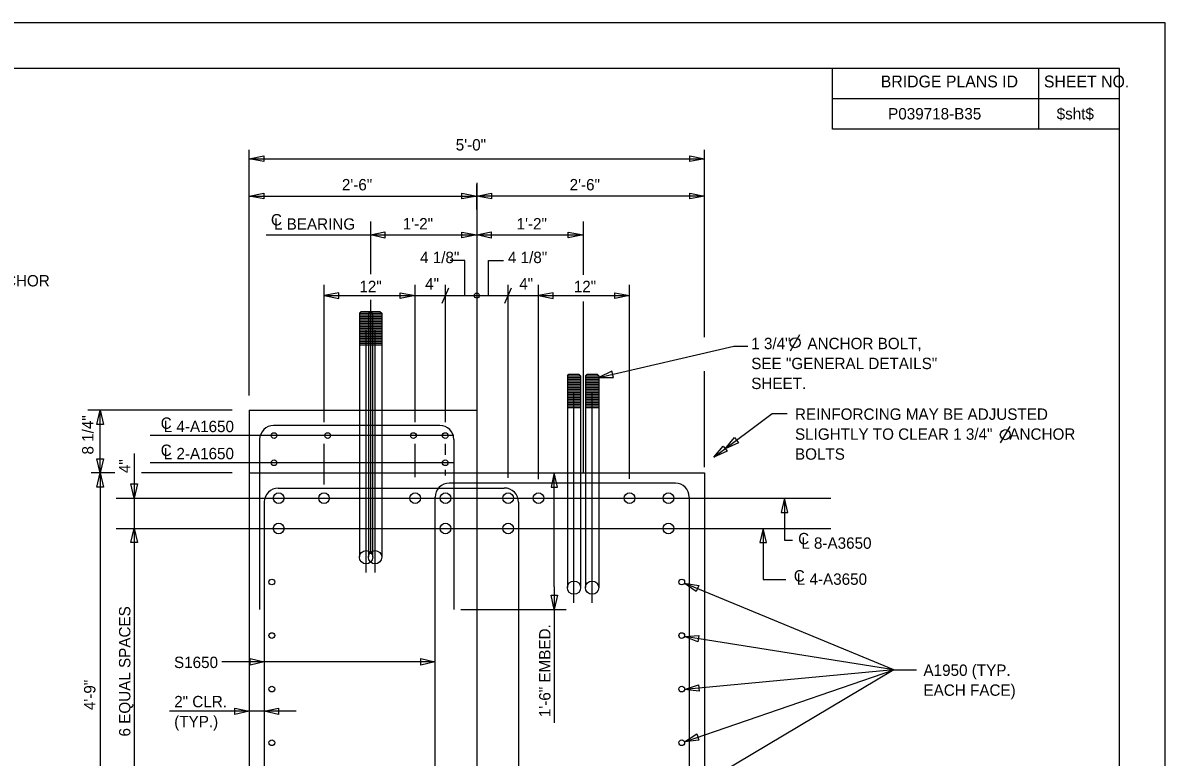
# Model space of a CAD drawing. Extents: x -133.1 to -97, y -1.7 to 20.3.
# Drawn here: x -109.68 to -97.14, y 12.24 to 20.31 of the extents above; entities that cross this region are included whole.
import ezdxf

# ---------------------------------------------------------------- set-up
doc = ezdxf.new("R2010")
doc.units = 0
for name, color, linetype in [('BR_AUTO DIMENSION', 7, 'Continuous'), ('BR_BORDER LINES', 7, 'Continuous'), ('BR_CENTER LINES', 7, 'Continuous'), ('BR_CONCRETE', 7, 'Continuous'), ('BR_REBAR', 7, 'Continuous'), ('BR_STRUCTURAL STEEL', 7, 'Continuous'), ('BR_TEXT', 7, 'Continuous'), ('Level 31', 7, 'Continuous')]:
    doc.layers.add(name, color=color, linetype=linetype)

msp = doc.modelspace()

# ---------------------------------------------------------------- linework, layer by layer
at = {"layer": 'BR_AUTO DIMENSION'}
for p, q in [((-107.198, 16.216), (-107.198, 18.914)), ((-107.198, 18.817), (-102.198, 18.817)), ((-102.198, 16.857), (-102.198, 18.914)), ((-104.698, 18.258), (-104.698, 18.534)), ((-107.198, 18.406), (-104.698, 18.406)), ((-102.198, 18.406), (-104.698, 18.406)), ((-107.012, 17.979), (-103.532, 17.979)), ((-104.828, 17.699), (-104.992, 17.699)), ((-104.828, 17.314), (-104.828, 17.699)), ((-104.568, 17.314), (-104.568, 17.699)), ((-104.568, 17.699), (-104.404, 17.699)), ((-106.375, 15.923), (-106.375, 17.432)), ((-105.375, 15.923), (-105.375, 17.432)), ((-105.042, 15.923), (-105.042, 17.432)), ((-104.354, 15.313), (-104.354, 17.432)), ((-104.021, 15.297), (-104.021, 17.432)), ((-103.021, 15.302), (-103.021, 17.432)), ((-106.375, 17.314), (-103.021, 17.314)), ((-105.079, 17.231), (-105.005, 17.397)), ((-104.392, 17.231), (-104.317, 17.397)), ((-103.359, 16.414), (-101.877, 16.758)), ((-101.877, 16.758), (-101.723, 16.758)), ((-102.198, 15.429), (-102.198, 16.483)), ((-107.384, 16.054), (-108.969, 16.054)), ((-108.833, 15.366), (-108.833, 16.054)), ((-106.375, 15.239), (-106.375, 15.684)), ((-105.375, 15.319), (-105.375, 15.684)), ((-105.042, 15.565), (-105.042, 15.684)), ((-108.459, 15.581), (-108.459, 10.355)), ((-108.671, 15.366), (-108.931, 15.366)), ((-108.833, 15.366), (-108.834, 10.616)), ((-107.385, 15.366), (-108.38, 15.366)), ((-105.042, 15.336), (-105.042, 15.401)), ((-103.847, 14.116), (-103.847, 15.366)), ((-101.555, 14.756), (-101.555, 14.194)), ((-101.555, 14.194), (-101.304, 14.194)), ((-103.847, 14.116), (-103.847, 12.621)), ((-100.118, 13.205), (-102.42, 14.155)), ((-104.872, 13.866), (-103.716, 13.866)), ((-100.118, 13.205), (-102.418, 13.57)), ((-105.157, 13.292), (-107.497, 13.292)), ((-100.118, 13.205), (-102.422, 11.832)), ((-100.118, 13.205), (-102.417, 12.989)), ((-106.68, 12.748), (-108.072, 12.748))]:
    msp.add_line(p, q, dxfattribs=at)
for points in [[(-107.036, 18.785), (-107.198, 18.817), (-107.036, 18.848)], [(-102.361, 18.848), (-102.198, 18.817), (-102.361, 18.785)], [(-107.036, 18.375), (-107.198, 18.406), (-107.036, 18.437)], [(-104.861, 18.437), (-104.698, 18.406), (-104.861, 18.375)], [(-104.536, 18.375), (-104.698, 18.406), (-104.536, 18.437)], [(-102.361, 18.437), (-102.198, 18.406), (-102.361, 18.375)], [(-105.709, 17.943), (-105.865, 17.979), (-105.709, 18.015)], [(-104.861, 18.01), (-104.698, 17.979), (-104.861, 17.948)], [(-104.542, 17.943), (-104.698, 17.979), (-104.542, 18.015)], [(-103.694, 18.01), (-103.532, 17.979), (-103.694, 17.948)], [(-106.213, 17.345), (-106.375, 17.314), (-106.213, 17.283)], [(-105.538, 17.345), (-105.375, 17.314), (-105.538, 17.283)], [(-103.859, 17.345), (-104.021, 17.314), (-103.859, 17.283)], [(-103.184, 17.345), (-103.021, 17.314), (-103.184, 17.283)], [(-103.215, 16.484), (-103.359, 16.414), (-103.199, 16.414)], [(-108.869, 15.898), (-108.833, 16.054), (-108.797, 15.898)], [(-101.824, 15.697), (-101.971, 15.632), (-101.868, 15.755)], [(-101.949, 15.604), (-102.096, 15.539), (-101.993, 15.661)], [(-108.797, 15.522), (-108.833, 15.366), (-108.869, 15.522)], [(-108.869, 15.21), (-108.833, 15.366), (-108.797, 15.21)], [(-103.811, 15.21), (-103.847, 15.366), (-103.883, 15.21)], [(-108.423, 15.245), (-108.459, 15.089), (-108.495, 15.245)], [(-101.283, 14.933), (-101.319, 15.089), (-101.355, 14.933)], [(-108.495, 14.6), (-108.459, 14.756), (-108.423, 14.6)], [(-101.519, 14.6), (-101.555, 14.756), (-101.591, 14.6)], [(-102.289, 14.062), (-102.42, 14.155), (-102.262, 14.129)], [(-103.811, 14.022), (-103.847, 13.866), (-103.883, 14.022)], [(-102.27, 13.51), (-102.418, 13.57), (-102.259, 13.581)], [(-107.187, 13.328), (-107.032, 13.292), (-107.187, 13.256)], [(-105.312, 13.328), (-105.157, 13.292), (-105.312, 13.256)], [(-102.258, 12.968), (-102.417, 12.989), (-102.265, 13.039)], [(-107.354, 12.784), (-107.198, 12.748), (-107.354, 12.712)], [(-106.876, 12.712), (-107.032, 12.748), (-106.876, 12.784)], [(-102.259, 12.43), (-102.419, 12.414), (-102.283, 12.499)]]:
    msp.add_lwpolyline(points, close=True, dxfattribs=at)
for points in [[(-102.096, 15.539), (-101.455, 16.018), (-101.29, 16.018)], [(-101.319, 15.089), (-101.319, 14.626), (-101.231, 14.626)], [(-102.419, 12.414), (-100.118, 13.205), (-99.87, 13.205)]]:
    msp.add_lwpolyline(points, dxfattribs=at)
msp.add_circle((-104.698, 17.314), 0.0285, dxfattribs=at)
at = {"layer": 'BR_BORDER LINES'}
for p, q in [((-97.642, 19.809), (-131.308, 19.809)), ((-100.794, 19.142), (-100.794, 19.809)), ((-98.528, 19.142), (-98.528, 19.809)), ((-97.642, -1.191), (-97.642, 19.809)), ((-100.794, 19.479), (-97.642, 19.479)), ((-98.528, 19.479), (-97.642, 19.479)), ((-97.642, 19.142), (-100.794, 19.142))]:
    msp.add_line(p, q, dxfattribs=at)
at = {"layer": 'BR_CENTER LINES'}
for p, q in [((-104.698, 18.553), (-104.698, 7.924)), ((-105.865, 18.126), (-105.865, 17.549)), ((-103.532, 18.126), (-103.532, 17.543)), ((-105.865, 17.266), (-105.865, 16.054)), ((-103.532, 17.249), (-103.532, 15.366)), ((-105.914, 16.054), (-105.914, 16.926)), ((-105.815, 16.054), (-105.815, 16.926)), ((-103.631, 15.366), (-103.631, 16.239)), ((-103.432, 15.366), (-103.432, 16.239)), ((-105.914, 14.274), (-105.914, 16.054)), ((-105.865, 16.054), (-105.865, 14.477)), ((-105.815, 14.274), (-105.815, 16.054)), ((-104.95, 15.776), (-108.284, 15.776)), ((-104.95, 15.478), (-108.284, 15.478)), ((-103.631, 13.94), (-103.631, 15.366)), ((-103.432, 13.94), (-103.432, 15.366)), ((-108.656, 15.089), (-100.812, 15.089)), ((-108.656, 14.756), (-100.812, 14.756))]:
    msp.add_line(p, q, dxfattribs=at)
at = {"layer": 'BR_CONCRETE'}
for p, q in [((-107.198, 16.054), (-107.198, 10.616)), ((-107.198, 16.054), (-104.698, 16.054)), ((-104.698, 16.054), (-104.698, 15.366)), ((-107.198, 15.366), (-102.198, 15.366)), ((-102.198, 15.366), (-102.198, 10.616))]:
    msp.add_line(p, q, dxfattribs=at)
at = {"layer": 'BR_REBAR'}
for p, q in [((-105.104, 15.887), (-106.929, 15.887)), ((-107.082, 15.733), (-107.082, 13.866)), ((-104.95, 15.733), (-104.95, 13.866)), ((-106.878, 15.2), (-104.396, 15.2)), ((-102.519, 15.254), (-105, 15.254)), ((-105.157, 15.098), (-105.157, 10.912)), ((-102.365, 15.096), (-102.365, 10.91)), ((-107.032, 15.046), (-107.032, 10.937)), ((-104.24, 15.044), (-104.24, 10.939))]:
    msp.add_line(p, q, dxfattribs=at)
for centre, radius in [((-106.924, 15.776), 0.0313), ((-106.335, 15.776), 0.0313), ((-105.394, 15.776), 0.0313), ((-105.044, 15.776), 0.0313), ((-106.924, 15.478), 0.0313), ((-105.044, 15.478), 0.0313), ((-106.873, 15.089), 0.0588), ((-106.375, 15.089), 0.0588), ((-105.375, 15.089), 0.0588), ((-105.042, 15.089), 0.0588), ((-104.354, 15.089), 0.0588), ((-104.021, 15.089), 0.0588), ((-103.021, 15.089), 0.0588), ((-102.594, 15.089), 0.0588), ((-106.873, 14.756), 0.0588), ((-105.042, 14.756), 0.0588), ((-104.354, 14.756), 0.0588), ((-102.594, 14.756), 0.0588), ((-106.948, 14.168), 0.0313), ((-102.448, 14.168), 0.0313), ((-106.948, 13.58), 0.0313), ((-102.448, 13.58), 0.0313), ((-106.948, 12.992), 0.0313), ((-102.448, 12.992), 0.0313), ((-106.948, 12.403), 0.0313), ((-102.448, 12.403), 0.0313)]:
    msp.add_circle(centre, radius, dxfattribs=at)
for centre, start, end in [((-106.926, 15.731), 91.025, 178.975), ((-105.106, 15.731), 1.025, 88.975), ((-106.875, 15.044), 91.025, 178.975), ((-105, 15.098), 90, 180), ((-104.396, 15.044), 0, 90), ((-102.521, 15.098), 1.025, 88.975)]:
    msp.add_arc(centre, 0.156, start, end, dxfattribs=at)
at = {"layer": 'BR_STRUCTURAL STEEL'}
for p, q in [((-105.987, 17.119), (-105.969, 17.138)), ((-105.987, 17.119), (-105.842, 17.119)), ((-105.987, 17.119), (-105.987, 16.054)), ((-105.987, 17.101), (-105.842, 17.101)), ((-105.987, 17.083), (-105.842, 17.083)), ((-105.987, 17.065), (-105.842, 17.065)), ((-105.969, 17.138), (-105.86, 17.138)), ((-105.888, 17.119), (-105.87, 17.138)), ((-105.888, 17.119), (-105.742, 17.119)), ((-105.888, 17.119), (-105.888, 16.054)), ((-105.888, 17.101), (-105.742, 17.101)), ((-105.888, 17.083), (-105.742, 17.083)), ((-105.888, 17.065), (-105.742, 17.065)), ((-105.87, 17.138), (-105.761, 17.138)), ((-105.86, 17.138), (-105.842, 17.119)), ((-105.842, 17.119), (-105.842, 16.054)), ((-105.761, 17.138), (-105.742, 17.119)), ((-105.742, 17.119), (-105.742, 16.054)), ((-105.987, 17.046), (-105.842, 17.046)), ((-105.987, 17.028), (-105.842, 17.028)), ((-105.987, 17.01), (-105.842, 17.01)), ((-105.987, 16.992), (-105.842, 16.992)), ((-105.987, 16.974), (-105.842, 16.974)), ((-105.987, 16.955), (-105.842, 16.955)), ((-105.987, 16.937), (-105.842, 16.937)), ((-105.888, 17.046), (-105.742, 17.046)), ((-105.888, 17.028), (-105.742, 17.028)), ((-105.888, 17.01), (-105.742, 17.01)), ((-105.888, 16.992), (-105.742, 16.992)), ((-105.888, 16.974), (-105.742, 16.974)), ((-105.888, 16.955), (-105.742, 16.955)), ((-105.888, 16.937), (-105.742, 16.937)), ((-105.987, 16.919), (-105.842, 16.919)), ((-105.987, 16.901), (-105.842, 16.901)), ((-105.987, 16.882), (-105.842, 16.882)), ((-105.987, 16.864), (-105.842, 16.864)), ((-105.987, 16.846), (-105.842, 16.846)), ((-105.987, 16.828), (-105.842, 16.828)), ((-105.987, 16.809), (-105.842, 16.809)), ((-105.888, 16.919), (-105.742, 16.919)), ((-105.888, 16.901), (-105.742, 16.901)), ((-105.888, 16.882), (-105.742, 16.882)), ((-105.888, 16.864), (-105.742, 16.864)), ((-105.888, 16.846), (-105.742, 16.846)), ((-105.888, 16.828), (-105.742, 16.828)), ((-105.888, 16.809), (-105.742, 16.809)), ((-105.987, 16.791), (-105.842, 16.791)), ((-105.987, 16.773), (-105.842, 16.773)), ((-105.888, 16.791), (-105.742, 16.791)), ((-105.888, 16.773), (-105.742, 16.773)), ((-103.704, 16.432), (-103.686, 16.45)), ((-103.704, 16.432), (-103.559, 16.432)), ((-103.704, 16.432), (-103.704, 15.366)), ((-103.686, 16.45), (-103.577, 16.45)), ((-103.577, 16.45), (-103.559, 16.432)), ((-103.559, 16.432), (-103.559, 15.366)), ((-103.505, 16.432), (-103.486, 16.45)), ((-103.505, 16.432), (-103.359, 16.432)), ((-103.505, 16.432), (-103.505, 15.366)), ((-103.486, 16.45), (-103.377, 16.45)), ((-103.377, 16.45), (-103.359, 16.432)), ((-103.359, 16.432), (-103.359, 15.366)), ((-103.704, 16.414), (-103.559, 16.414)), ((-103.704, 16.396), (-103.559, 16.396)), ((-103.704, 16.377), (-103.559, 16.377)), ((-103.704, 16.359), (-103.559, 16.359)), ((-103.704, 16.341), (-103.559, 16.341)), ((-103.704, 16.323), (-103.559, 16.323)), ((-103.704, 16.304), (-103.559, 16.304)), ((-103.505, 16.414), (-103.359, 16.414)), ((-103.505, 16.396), (-103.359, 16.396)), ((-103.505, 16.377), (-103.359, 16.377)), ((-103.505, 16.359), (-103.359, 16.359)), ((-103.505, 16.341), (-103.359, 16.341)), ((-103.505, 16.323), (-103.359, 16.323)), ((-103.505, 16.304), (-103.359, 16.304)), ((-103.704, 16.286), (-103.559, 16.286)), ((-103.704, 16.268), (-103.559, 16.268)), ((-103.704, 16.25), (-103.559, 16.25)), ((-103.704, 16.231), (-103.559, 16.231)), ((-103.704, 16.213), (-103.559, 16.213)), ((-103.704, 16.195), (-103.559, 16.195)), ((-103.505, 16.286), (-103.359, 16.286)), ((-103.505, 16.268), (-103.359, 16.268)), ((-103.505, 16.25), (-103.359, 16.25)), ((-103.505, 16.231), (-103.359, 16.231)), ((-103.505, 16.213), (-103.359, 16.213)), ((-103.505, 16.195), (-103.359, 16.195)), ((-105.987, 16.054), (-105.987, 14.443)), ((-105.888, 16.054), (-105.888, 14.443)), ((-105.842, 16.054), (-105.842, 14.44)), ((-105.742, 16.054), (-105.742, 14.44)), ((-103.704, 16.177), (-103.559, 16.177)), ((-103.704, 16.159), (-103.559, 16.159)), ((-103.704, 16.14), (-103.559, 16.14)), ((-103.704, 16.122), (-103.559, 16.122)), ((-103.704, 16.104), (-103.559, 16.104)), ((-103.704, 16.086), (-103.559, 16.086)), ((-103.505, 16.177), (-103.359, 16.177)), ((-103.505, 16.159), (-103.359, 16.159)), ((-103.505, 16.14), (-103.359, 16.14)), ((-103.505, 16.122), (-103.359, 16.122)), ((-103.505, 16.104), (-103.359, 16.104)), ((-103.505, 16.086), (-103.359, 16.086)), ((-103.704, 15.366), (-103.704, 14.109)), ((-103.559, 15.366), (-103.559, 14.106)), ((-103.505, 15.366), (-103.504, 14.109)), ((-103.359, 15.366), (-103.359, 14.106))]:
    msp.add_line(p, q, dxfattribs=at)
for centre in [(-105.914, 14.44), (-105.815, 14.44), (-103.631, 14.106), (-103.432, 14.106)]:
    msp.add_circle(centre, 0.0729, dxfattribs=at)
at = {"layer": 'BR_TEXT'}
for p, q in [((-101.255, 16.705), (-101.15, 16.886)), ((-98.949, 15.695), (-98.844, 15.877))]:
    msp.add_line(p, q, dxfattribs=at)
for centre in [(-101.202, 16.796), (-98.896, 15.786)]:
    msp.add_circle(centre, 0.055, dxfattribs=at)
at = {"layer": 'Level 31'}
msp.add_lwpolyline([(-133.141, -1.691), (-97.141, -1.691), (-97.141, 20.309), (-133.141, 20.309)], close=True, dxfattribs=at)

# ---------------------------------------------------------------- texts
at = {"layer": 'BR_AUTO DIMENSION'}
for s, p in [('5\'-0"', (-104.929, 18.907)), ('2\'-6"', (-106.179, 18.469)), ('2\'-6"', (-103.679, 18.469)), ('4 1/8"', (-105.321, 17.67)), ('4 1/8"', (-104.356, 17.67)), ('12"', (-105.987, 17.351)), ('4"', (-105.265, 17.38)), ('4"', (-104.232, 17.38)), ('12"', (-103.633, 17.351))]:
    msp.add_text(s, height=0.125, dxfattribs=at).set_placement(p)
at = {"layer": 'BR_TEXT'}
for s, height, p in [('BRIDGE PLANS ID', 0.13, (-100.263, 19.6)), ('SHEET NO.', 0.13, (-98.472, 19.6)), ('P039718-B35', 0.125, (-100.182, 19.248)), ('$sht$', 0.125, (-98.332, 19.248))]:
    msp.add_text(s, height=height, dxfattribs=at).set_placement(p)
for s, rotation, p in [('C', 360, (-106.958, 18.084)), ('L BEARING', 360, (-106.925, 18.037)), ('1\'-2"', 360, (-105.511, 18.04)), ('1\'-2"', 360, (-104.261, 18.04)), ('SLIGHTLY TO CLEAR 1 3/4"    ANCHOR', 360, (-112.464, 17.414)), ('1 3/4"    ANCHOR BOLT, ', 360, (-101.685, 16.725)), ('SEE "GENERAL DETAILS"', 360, (-101.685, 16.506)), ('SHEET.', 360, (-101.685, 16.287)), ('REINFORCING MAY BE ADJUSTED', 360, (-101.205, 15.949)), ('8 1/4"', 90, (-108.906, 15.568)), ('C', 360, (-108.168, 15.85)), ('L 4-A1650', 360, (-108.135, 15.814)), ('SLIGHTLY TO CLEAR 1 3/4"    ANCHOR', 360, (-101.205, 15.73)), ('C', 360, (-108.168, 15.552)), ('L 2-A1650', 360, (-108.135, 15.516)), ('BOLTS', 360, (-101.205, 15.511)), ('4"', 90, (-108.501, 15.364)), ('C', 360, (-101.17, 14.582)), ('L 8-A3650', 360, (-101.136, 14.533)), ('C', 360, (-101.218, 14.173)), ('L 4-A3650', 360, (-101.185, 14.137)), ('6 EQUAL SPACES', 90, (-108.501, 12.471)), ('1\'-6" EMBED.', 90, (-103.889, 12.684)), ('S1650', 360, (-108.022, 13.223)), ('A1950 (TYP.', 360, (-99.794, 13.137)), ('4\'-9"', 90, (-108.885, 12.761)), ('EACH FACE)', 360, (-99.794, 12.918)), ('2" CLR.', 360, (-108.02, 12.792)), ('(TYP.)', 360, (-108.02, 12.573))]:
    msp.add_text(s, height=0.125, rotation=rotation, dxfattribs=at).set_placement(p)

doc.saveas('drawing.dxf')
